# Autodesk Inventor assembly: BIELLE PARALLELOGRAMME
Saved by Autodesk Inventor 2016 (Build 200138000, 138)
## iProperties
Created: 2013-10
Part Number: BIELLE PARALLELOGRAMME
Material: Générique
Document SubType Name: Assembly
Designer: Bruno
Author: Bruno
Sending System: SolidWorks 2013
Last Author: christophe
Last Saved: 2014-02-15
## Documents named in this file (3)
- D:\Cours\Systèmes\SI\Robot Haptique\Documentations_pedagogique\Modèle solidworks\Réel\BIELLE PARALLELOGRAMME.iam
- D:\Cours\Systèmes\SI\Robot Haptique\Documentations_pedagogique\Modèle solidworks\Réel\BIELLE PARALLELOGRAMME.ipt
- D:\Cours\Systèmes\SI\Robot Haptique\Documentations_pedagogique\Modèle solidworks\Réel\AXE BIELLE.ipt
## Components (3 placed, 2 different names)
1. BIELLE PARALLELOGRAMME:1
2. AXE BIELLE:1
3. AXE BIELLE:2
